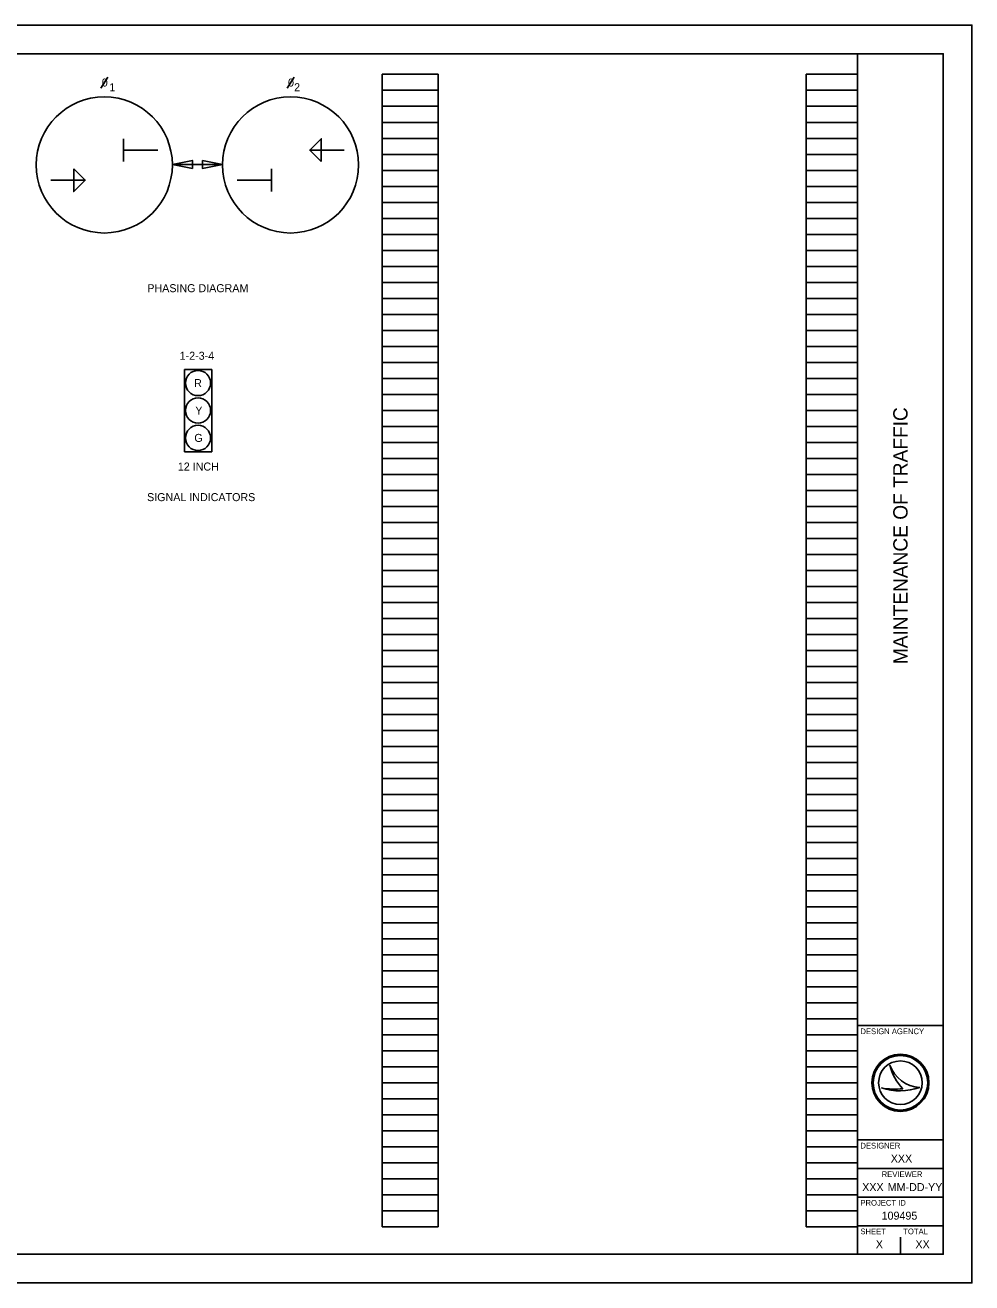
# Model space of a CAD drawing. Extents: x 0 to 59.9, y -1.6 to 22.
# Drawn here: x 17.43 to 34, y 0 to 22 of the extents above; entities that cross this region are included whole.
import ezdxf

# ---------------------------------------------------------------- set-up
doc = ezdxf.new("R2010")
doc.units = 0
for name, color, linetype in [('Default', 7, 'Continuous'), ('SG_P_Heads', 7, 'Continuous'), ('SH_Border', 7, 'Continuous'), ('SH_Cut_Line', 7, 'Continuous'), ('SH_Data', 7, 'Continuous'), ('TX_P_1', 7, 'Continuous')]:
    doc.layers.add(name, color=color, linetype=linetype)

msp = doc.modelspace()

# ---------------------------------------------------------------- linework, layer by layer
at = {"layer": 'Default'}
for p, q in [((20.699, 15.976), (20.221, 15.976)), ((20.221, 15.976), (20.221, 14.534)), ((20.699, 14.534), (20.699, 15.976)), ((20.221, 14.534), (20.699, 14.534))]:
    msp.add_line(p, q, dxfattribs=at)
for centre in [(20.459, 15.739), (20.459, 15.259), (20.459, 14.78)]:
    msp.add_circle(centre, 0.22, dxfattribs=at)
at = {"layer": 'SG_P_Heads'}
for p, q in [((19.154, 20.014), (19.154, 19.614)), ((19.755, 19.814), (19.154, 19.814)), ((23.014, 19.814), (22.414, 19.814)), ((21.744, 19.089), (21.744, 19.489)), ((17.884, 19.289), (18.485, 19.289)), ((21.143, 19.289), (21.744, 19.289))]:
    msp.add_line(p, q, dxfattribs=at)
for points in [[(22.614, 19.614), (22.414, 19.814), (22.614, 20.014)], [(20.362, 19.493), (20.012, 19.563), (20.362, 19.633)], [(20.535, 19.633), (20.885, 19.563), (20.535, 19.493)], [(18.285, 19.489), (18.485, 19.289), (18.285, 19.089)]]:
    msp.add_lwpolyline(points, close=True, dxfattribs=at)
at = {"layer": 'SH_Border'}
for p, q in [((32, 0.5), (32, 21.5)), ((32, 4.5), (33.5, 4.5)), ((32, 2.5), (33.5, 2.5)), ((32, 2), (33.5, 2)), ((32, 1.5), (33.5, 1.5)), ((32, 1), (33.5, 1))]:
    msp.add_line(p, q, dxfattribs=at)
msp.add_lwpolyline([(1.5, 21.5), (33.5, 21.5), (33.5, 0.5), (1.5, 0.5)], close=True, dxfattribs=at)
at = {"layer": 'SH_Cut_Line'}
msp.add_lwpolyline([(0, 0), (34, 0), (34, 22), (0, 22)], close=True, dxfattribs=at)
at = {"layer": 'SH_Data'}
for p, q in [((23.68, 0.98), (23.68, 21.14)), ((23.68, 21.14), (24.66, 21.14)), ((24.66, 0.98), (24.66, 21.14)), ((31.1, 0.98), (31.1, 21.14)), ((31.1, 21.14), (32, 21.14)), ((32, 0.98), (32, 21.14)), ((23.68, 20.86), (24.66, 20.86)), ((31.1, 20.86), (32, 20.86)), ((23.68, 20.58), (24.66, 20.58)), ((31.1, 20.58), (32, 20.58)), ((23.68, 20.3), (24.66, 20.3)), ((31.1, 20.3), (32, 20.3)), ((23.68, 20.02), (24.66, 20.02)), ((31.1, 20.02), (32, 20.02)), ((23.68, 19.74), (24.66, 19.74)), ((31.1, 19.74), (32, 19.74)), ((20.885, 19.563), (20.012, 19.563)), ((23.68, 19.46), (24.66, 19.46)), ((31.1, 19.46), (32, 19.46)), ((23.68, 19.18), (24.66, 19.18)), ((31.1, 19.18), (32, 19.18)), ((23.68, 18.9), (24.66, 18.9)), ((31.1, 18.9), (32, 18.9)), ((23.68, 18.62), (24.66, 18.62)), ((31.1, 18.62), (32, 18.62)), ((23.68, 18.34), (24.66, 18.34)), ((31.1, 18.34), (32, 18.34)), ((23.68, 18.06), (24.66, 18.06)), ((31.1, 18.06), (32, 18.06)), ((23.68, 17.78), (24.66, 17.78)), ((31.1, 17.78), (32, 17.78)), ((23.68, 17.5), (24.66, 17.5)), ((31.1, 17.5), (32, 17.5)), ((23.68, 17.22), (24.66, 17.22)), ((31.1, 17.22), (32, 17.22)), ((23.68, 16.94), (24.66, 16.94)), ((31.1, 16.94), (32, 16.94)), ((23.68, 16.66), (24.66, 16.66)), ((31.1, 16.66), (32, 16.66)), ((23.68, 16.38), (24.66, 16.38)), ((31.1, 16.38), (32, 16.38)), ((23.68, 16.1), (24.66, 16.1)), ((31.1, 16.1), (32, 16.1)), ((23.68, 15.82), (24.66, 15.82)), ((31.1, 15.82), (32, 15.82)), ((23.68, 15.54), (24.66, 15.54)), ((31.1, 15.54), (32, 15.54)), ((23.68, 15.26), (24.66, 15.26)), ((31.1, 15.26), (32, 15.26)), ((23.68, 14.98), (24.66, 14.98)), ((31.1, 14.98), (32, 14.98)), ((23.68, 14.7), (24.66, 14.7)), ((31.1, 14.7), (32, 14.7)), ((23.68, 14.42), (24.66, 14.42)), ((31.1, 14.42), (32, 14.42)), ((23.68, 14.14), (24.66, 14.14)), ((31.1, 14.14), (32, 14.14)), ((23.68, 13.86), (24.66, 13.86)), ((31.1, 13.86), (32, 13.86)), ((23.68, 13.58), (24.66, 13.58)), ((31.1, 13.58), (32, 13.58)), ((23.68, 13.3), (24.66, 13.3)), ((31.1, 13.3), (32, 13.3)), ((23.68, 13.02), (24.66, 13.02)), ((31.1, 13.02), (32, 13.02)), ((23.68, 12.74), (24.66, 12.74)), ((31.1, 12.74), (32, 12.74)), ((23.68, 12.46), (24.66, 12.46)), ((31.1, 12.46), (32, 12.46)), ((23.68, 12.18), (24.66, 12.18)), ((31.1, 12.18), (32, 12.18)), ((23.68, 11.9), (24.66, 11.9)), ((31.1, 11.9), (32, 11.9)), ((23.68, 11.62), (24.66, 11.62)), ((31.1, 11.62), (32, 11.62)), ((23.68, 11.34), (24.66, 11.34)), ((31.1, 11.34), (32, 11.34)), ((23.68, 11.06), (24.66, 11.06)), ((31.1, 11.06), (32, 11.06)), ((23.68, 10.78), (24.66, 10.78)), ((31.1, 10.78), (32, 10.78)), ((23.68, 10.5), (24.66, 10.5)), ((31.1, 10.5), (32, 10.5)), ((23.68, 10.22), (24.66, 10.22)), ((31.1, 10.22), (32, 10.22)), ((23.68, 9.94), (24.66, 9.94)), ((31.1, 9.94), (32, 9.94)), ((23.68, 9.66), (24.66, 9.66)), ((31.1, 9.66), (32, 9.66)), ((23.68, 9.38), (24.66, 9.38)), ((31.1, 9.38), (32, 9.38)), ((23.68, 9.1), (24.66, 9.1)), ((31.1, 9.1), (32, 9.1)), ((23.68, 8.82), (24.66, 8.82)), ((31.1, 8.82), (32, 8.82)), ((23.68, 8.54), (24.66, 8.54)), ((31.1, 8.54), (32, 8.54)), ((23.68, 8.26), (24.66, 8.26)), ((31.1, 8.26), (32, 8.26)), ((23.68, 7.98), (24.66, 7.98)), ((31.1, 7.98), (32, 7.98)), ((23.68, 7.7), (24.66, 7.7)), ((31.1, 7.7), (32, 7.7)), ((23.68, 7.42), (24.66, 7.42)), ((31.1, 7.42), (32, 7.42)), ((23.68, 7.14), (24.66, 7.14)), ((31.1, 7.14), (32, 7.14)), ((23.68, 6.86), (24.66, 6.86)), ((31.1, 6.86), (32, 6.86)), ((23.68, 6.58), (24.66, 6.58)), ((31.1, 6.58), (32, 6.58)), ((23.68, 6.3), (24.66, 6.3)), ((31.1, 6.3), (32, 6.3)), ((23.68, 6.02), (24.66, 6.02)), ((31.1, 6.02), (32, 6.02)), ((23.68, 5.74), (24.66, 5.74)), ((31.1, 5.74), (32, 5.74)), ((23.68, 5.46), (24.66, 5.46)), ((31.1, 5.46), (32, 5.46)), ((23.68, 5.18), (24.66, 5.18)), ((31.1, 5.18), (32, 5.18)), ((23.68, 4.9), (24.66, 4.9)), ((31.1, 4.9), (32, 4.9)), ((23.68, 4.62), (24.66, 4.62)), ((31.1, 4.62), (32, 4.62)), ((23.68, 4.34), (24.66, 4.34)), ((31.1, 4.34), (32, 4.34)), ((23.68, 4.06), (24.66, 4.06)), ((31.1, 4.06), (32, 4.06)), ((23.68, 3.78), (24.66, 3.78)), ((31.1, 3.78), (32, 3.78)), ((32.567, 3.81), (32.567, 3.81)), ((23.68, 3.5), (24.66, 3.5)), ((31.1, 3.5), (32, 3.5)), ((32.417, 3.41), (32.417, 3.41)), ((32.75, 3.5), (32.75, 3.5)), ((33.087, 3.419), (33.087, 3.419)), ((23.68, 3.22), (24.66, 3.22)), ((31.1, 3.22), (32, 3.22)), ((23.68, 2.94), (24.66, 2.94)), ((31.1, 2.94), (32, 2.94)), ((23.68, 2.66), (24.66, 2.66)), ((31.1, 2.66), (32, 2.66)), ((23.68, 2.38), (24.66, 2.38)), ((31.1, 2.38), (32, 2.38)), ((23.68, 2.1), (24.66, 2.1)), ((31.1, 2.1), (32, 2.1)), ((23.68, 1.82), (24.66, 1.82)), ((31.1, 1.82), (32, 1.82)), ((23.68, 1.54), (24.66, 1.54)), ((31.1, 1.54), (32, 1.54)), ((23.68, 1.26), (24.66, 1.26)), ((31.1, 1.26), (32, 1.26)), ((23.68, 0.98), (24.66, 0.98)), ((31.1, 0.98), (32, 0.98)), ((32.375, 0.675), (32.375, 0.675)), ((32.75, 0.5), (32.75, 0.8))]:
    msp.add_line(p, q, dxfattribs=at)
for centre, radius in [((18.819, 19.555), 1.191), ((22.078, 19.555), 1.191), ((32.75, 3.5), 0.5), ((32.75, 3.5), 0.477), ((32.75, 3.5), 0.477), ((32.75, 3.5), 0.382)]:
    msp.add_circle(centre, radius, dxfattribs=at)
for centre, radius, start, end in [((33.116, 3.998), 0.58, 198.9257, 198.9319), ((33.347, 3.97), 0.796, 191.6379, 191.6421), ((33.116, 3.998), 0.58, 198.9319, 267.1657), ((33.347, 3.97), 0.796, 191.6421, 226.0947), ((32.739, 4.37), 1.013, 251.4576, 290.0832), ((32.648, 4.654), 1.266, 259.4964, 259.4995), ((32.739, 4.37), 1.013, 251.4527, 251.4576), ((32.648, 4.654), 1.266, 259.4995, 276.6672)]:
    msp.add_arc(centre, radius, start, end, dxfattribs=at)
at = {"layer": 'TX_P_1'}
for p, q in [((18.883, 21.088), (18.758, 20.895)), ((22.143, 21.088), (22.017, 20.895))]:
    msp.add_line(p, q, dxfattribs=at)

# ---------------------------------------------------------------- texts
at = {"layer": 'Default'}
for s, p in [('R', (20.391, 15.669)), ('Y', (20.411, 15.189)), ('G', (20.395, 14.71)), ('SIGNAL INDICATORS', (19.568, 13.674))]:
    msp.add_text(s, height=0.14, dxfattribs=at).set_placement(p)
at = {"layer": 'SH_Data'}
for s, height, p in [('0', 0.14, (18.775, 20.926)), ('DESIGN AGENCY', 0.1, (32.05, 4.35)), ('DESIGNER', 0.1, (32.05, 2.35)), ('XXX', 0.14, (32.581, 2.105)), ('REVIEWER', 0.1, (32.422, 1.85)), ('XXX', 0.14, (32.081, 1.605)), ('MM-DD-YY', 0.14, (32.527, 1.605)), ('PROJECT ID', 0.1, (32.05, 1.35)), ('109495', 0.14, (32.421, 1.105)), ('SHEET', 0.1, (32.05, 0.85)), ('TOTAL', 0.1, (32.8, 0.85)), ('X', 0.14, (32.32, 0.605)), ('XX', 0.14, (33.013, 0.605))]:
    msp.add_text(s, height=height, dxfattribs=at).set_placement(p)
msp.add_text('MAINTENANCE OF TRAFFIC', height=0.25, rotation=90, dxfattribs=at).set_placement((32.875, 10.822))
at = {"layer": 'TX_P_1'}
for s, p in [('1', (18.908, 20.844)), ('0', (22.034, 20.926)), ('2', (22.141, 20.844)), ('PHASING DIAGRAM', (19.572, 17.329)), ('1-2-3-4', (20.138, 16.147)), ('12 INCH', (20.106, 14.209))]:
    msp.add_text(s, height=0.14, dxfattribs=at).set_placement(p)

doc.saveas('drawing.dxf')
